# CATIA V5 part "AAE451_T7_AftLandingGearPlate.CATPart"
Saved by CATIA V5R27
Part number: Aft Landing Gear Mount
Bounding box of the stored display mesh (mm): x -69.85 to 0, y -12.7 to 12.7, z -63.5 to 6.35
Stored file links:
  W:\AAE 451\Aft Landing Gear Mount.CATPart
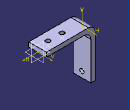
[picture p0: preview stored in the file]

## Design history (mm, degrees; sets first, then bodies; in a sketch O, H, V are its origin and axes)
Body1 (main body)
  Sketch1 on zx-plane, origin (0, 0, 0), H (-1, 0, 0), V (0, 0, 1)
    point P1 (0, 6.35)
    line L1 (0, 6.35) -> (0, 0)
    point P2 (0, 0)
    line L2 (0, 0) -> (63.5, 0)
    line L3 (63.5, 0) -> (63.5, -63.5)
    line L4 (63.5, -63.5) -> (69.85, -63.5)
    line L5 (69.85, -63.5) -> (69.85, 6.35)
    line L6 (69.85, 6.35) -> (0, 6.35)
    point P7 (0, 6.35)
    distance L3 L5 = 6.35
    length L1 = 6.35
    length L2 = 63.5
    length L3 = 63.5
    coincidence: P7 P1, P2 H, P2 V, L1 V
    parallelism: L1 L5, L1 L3
    perpendicularity: L3 L4, L1 L2, L1 L6
  Pad1: profile Sketch1, direction (0, 1, 0), length 12.7, mirrored extent
  Fillet1: radius 9.525, on edge [face of Pad1 from Sketch1.L3 | face of Pad1 from Sketch1.L2]
  Fillet2: radius 9.525, on edge [face of Pad1 from Sketch1.L6 | face of Pad1 from Sketch1.L5]
  Sketch2 on xy-plane, origin (0, 0, 0), H (1, 0, 0), V (0, 1, 0)
    point P1 (-15, 0)
    point P2 (-35, 0)
    distance P2 V = 35
    distance P1 V = 15
    coincidence: P1 H, P2 H
  Sketch3 on face of Pad1 from Sketch1.L3, origin (-63.5, 0, 0), H (0, 1, 0), V (0, 0, 1)
    point P1 (0, -55)
    distance P1 H = 55
    coincidence: P1 V
  Sketch4 on face of Pad1 from Sketch1.L2, origin (-44.6434, 8.3087, 0), H (1, 0, 0), V (0, -1, 0)
    point P1 (9.6434, 8.3087)
    reference projected point E1 (9.6434, 8.3087) from Sketch2.P2
    coincidence: E1 P1
  Hole1: placed by Sketch4, at (-35, 0, 0) direction (0, 0, 1), diameter 6.35, up to face of Pad1 from Sketch1.L6
  Sketch5 on face of Pad1 from Sketch1.L2, origin (-17.0286, -1.2635, 0), H (1, 0, 0), V (0, -1, 0)
    point P1 (2.0286, -1.2635)
    reference projected point E1 (2.0286, -1.2635) from Sketch2.P1
    coincidence: E1 P1
  Hole2: placed by Sketch5, at (-15, 0, 0) direction (0, 0, 1), diameter 6.35, up to face of Pad1 from Sketch1.L6
  Sketch6 on face of Pad1 from Sketch1.L3, origin (-63.5, -4.0021, -42.6353), H (0, 1, 0), V (0, 0, 1)
    point P1 (4.0021, -12.3647)
    reference projected point E1 (4.0021, -12.3647) from Sketch3
    coincidence: P1 E1
  Hole3: placed by Sketch6, at (-63.5, 0, -55) direction (-1, 0, 0), diameter 6.35, up to face of Pad1 from Sketch1.L5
